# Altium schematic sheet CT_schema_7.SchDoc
size 277 x 170 mm
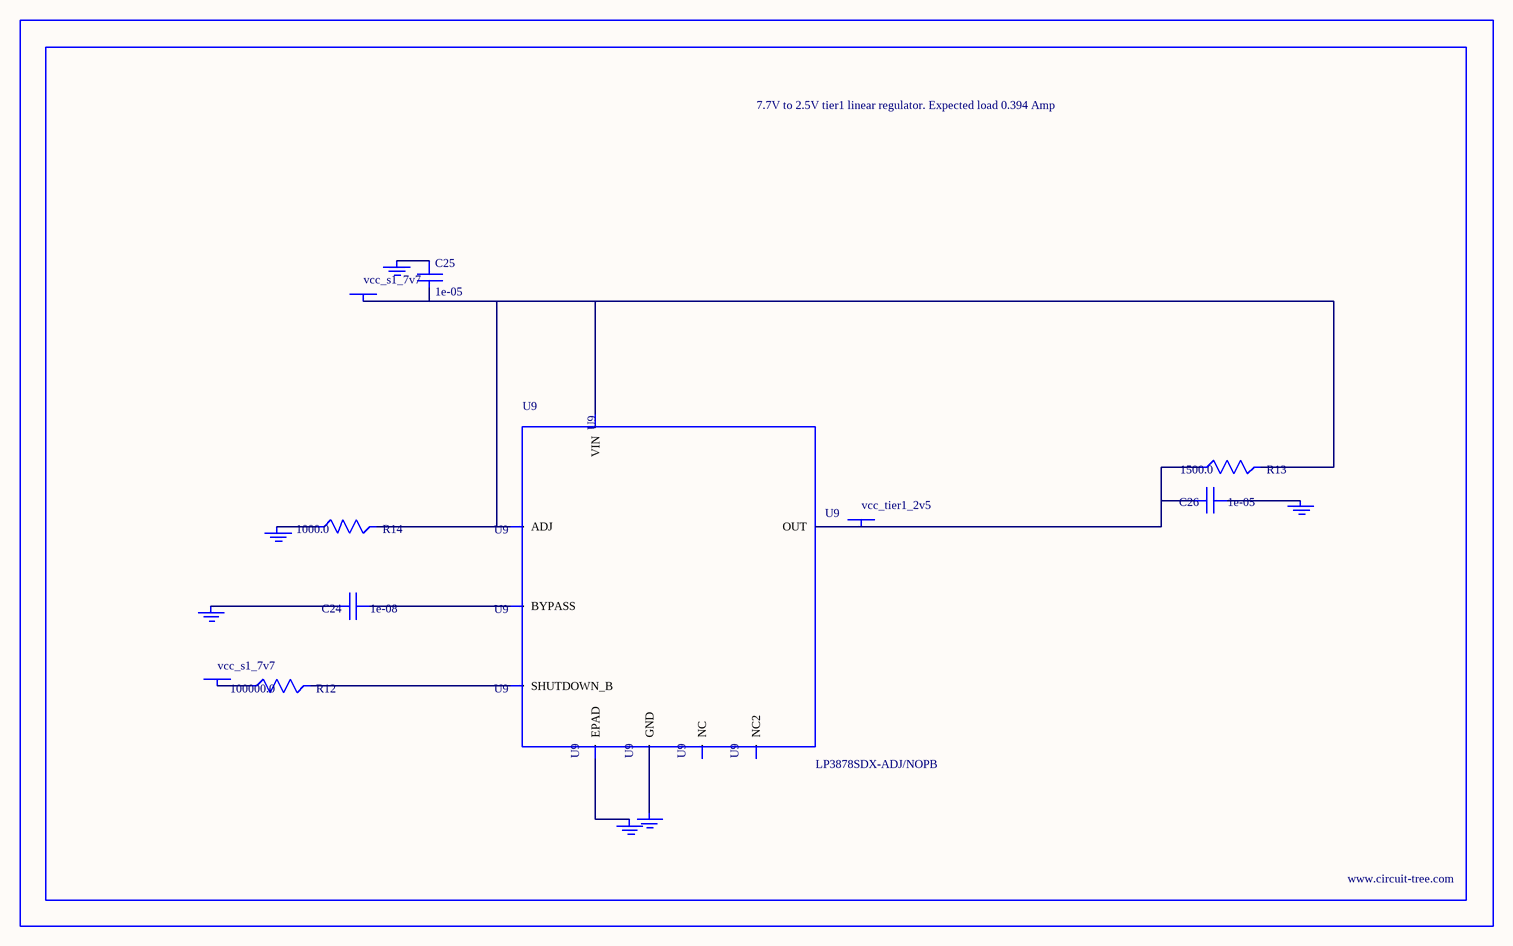
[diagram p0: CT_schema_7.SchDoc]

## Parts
BORDER6  (no value)
C24  1e-08  [C0402]
C25  1e-05  [C1206]
C26  1e-05  [C1210]
GND_INSTANCE_6_0  (no value)
GND_INSTANCE_6_1  (no value)
GND_INSTANCE_6_2  (no value)
GND_INSTANCE_6_3  (no value)
GND_INSTANCE_6_4  (no value)
GND_INSTANCE_6_5  (no value)
POWER_INSTANCE_6_0  vcc_s1_7v7
POWER_INSTANCE_6_1  vcc_s1_7v7
POWER_INSTANCE_6_2  vcc_tier1_2v5
R12  100000.0  [R0603]
R13  1500.0  [R0603]
R14  1000.0  [R0603]
U9  LP3878SDX-ADJ/NOPB  [WSON-8]

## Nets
NetC24_1: C24.1 U9.1(BYPASS)
NetC24_2: C24.2 GND_INSTANCE_6_0.0(GND)
NetC25_1: C25.1 GND_INSTANCE_6_1.0(GND)
NetC25_2: C25.2 POWER_INSTANCE_6_0.0(PWR) R13.2 R14.2 U9.4(VIN) U9.6(ADJ)
NetC26_1: C26.1 GND_INSTANCE_6_2.0(GND)
NetC26_2: C26.2 POWER_INSTANCE_6_2.0(PWR) R13.1 U9.5(OUT)
NetGND_INSTANCE_6_3_0: GND_INSTANCE_6_3.0(GND) R14.1
NetGND_INSTANCE_6_4_0: GND_INSTANCE_6_4.0(GND) U9.PAD(EPAD)
NetGND_INSTANCE_6_5_0: GND_INSTANCE_6_5.0(GND) U9.3(GND)
NetPOWER_INSTANCE_6_1_0: POWER_INSTANCE_6_1.0(PWR) R12.1
NetR12_2: R12.2 U9.8(SHUTDOWN_B)

Not connected (* = marked no-connect by the designer): U9 2(NC) 7(NC2)

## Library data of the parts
BORDER6 = BORDER_PAGE6
C24 = C0402C103K3RAC
C25 = C1206C106K3RACTU
C26 = GRM32DR61E106MA12L
GND_INSTANCE_6_0-GND_INSTANCE_6_5 = GND
POWER_INSTANCE_6_0-POWER_INSTANCE_6_2 = PWR
R12 = RC0603JR-07100KL
R13 = RC0603JR-071K5L
R14 = RC0603JR-071KL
